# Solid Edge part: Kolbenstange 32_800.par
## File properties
Username: ahadarics
Dokumentum tartalom típus: 0
Author: ahadarics
Last saved by: ahadarics
Revision: 97
Sűrűség: 0,000 kg/m^3
Pontosság: 0,990
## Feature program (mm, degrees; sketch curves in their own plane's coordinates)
base feature "unnamed BaseFeature 1"
thread "unnamed Thread 1"
chamfer "Letörés_1"  SetBackValue2 = 20 deg
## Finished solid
Body 1: solid body, 19 faces, 27 edges, 11 vertices.
  Faces by surface: plane 8, cylinder 5, cone 3, torus 3
  Edges by curve: circle 15, line 7, curve on surface 3, ellipse 2
Bounding box of the edges (mm; curved faces can reach further): 32.000 x 32.000 x 915.500, from (-16, -16, -50.25) to (16, 16, 865.25).
Cylindrical faces by radius (mm): R3.95 x1, R5 x1, R5.8 x1, R6 x1, R16 x1
Conical faces (half-angle, radius in mm at the cone's reference point): 20 deg R5 x1, 30 deg R5.9 x1, 60 deg R4.475 x1
Toroidal faces (ring radius, tube radius in mm): R4.35 r0.4 x2, R4.6 r1.2 x1
Planar faces by outward normal: +x 1, +z 3, -x 1, -z 1, oblique 2
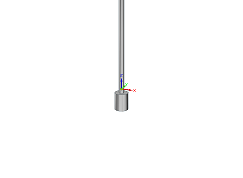
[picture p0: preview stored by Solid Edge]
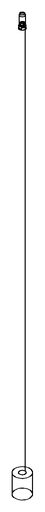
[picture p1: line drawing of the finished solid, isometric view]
